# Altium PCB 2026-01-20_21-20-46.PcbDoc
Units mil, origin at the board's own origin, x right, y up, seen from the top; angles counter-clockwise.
Board outline 2766 x 1978 mil, 4 copper layers (Top Layer, MidLayer1, MidLayer2, Bottom Layer); 17 components, 9 nets, 37 pads, 37 vias.
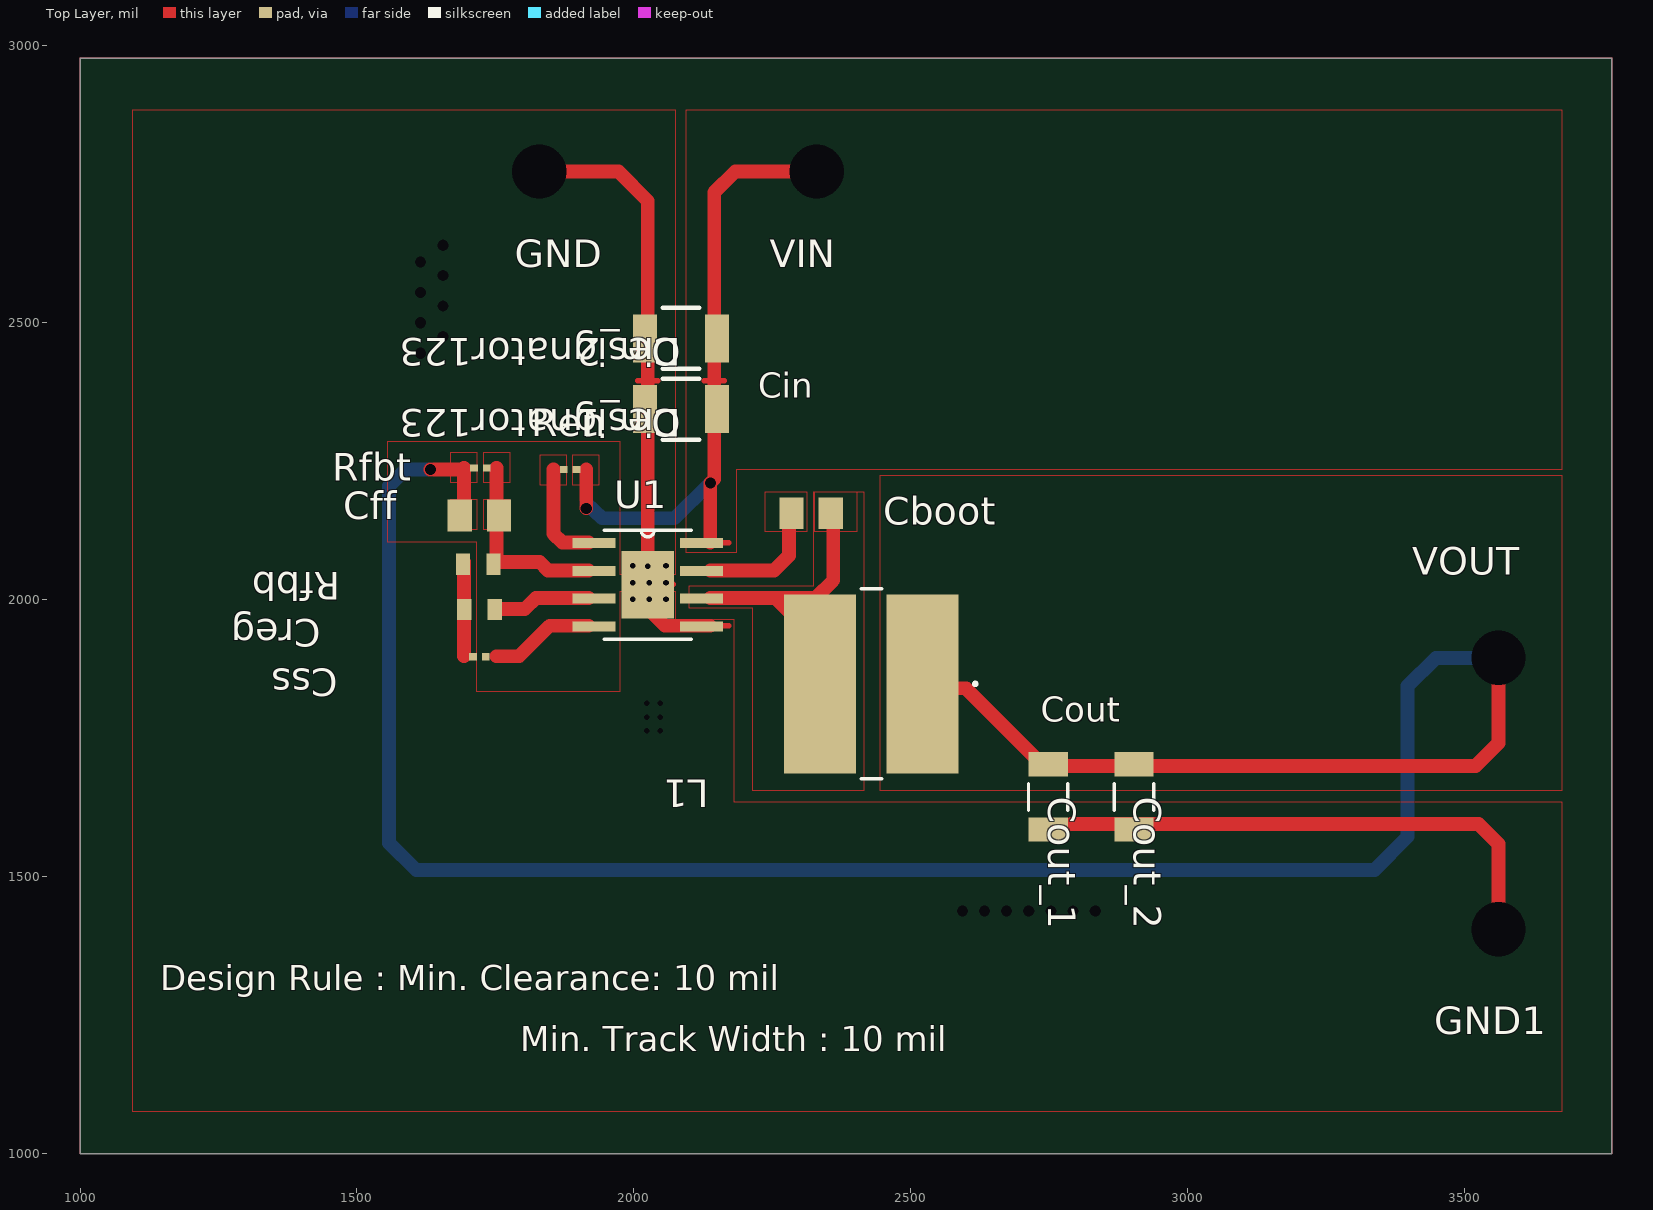
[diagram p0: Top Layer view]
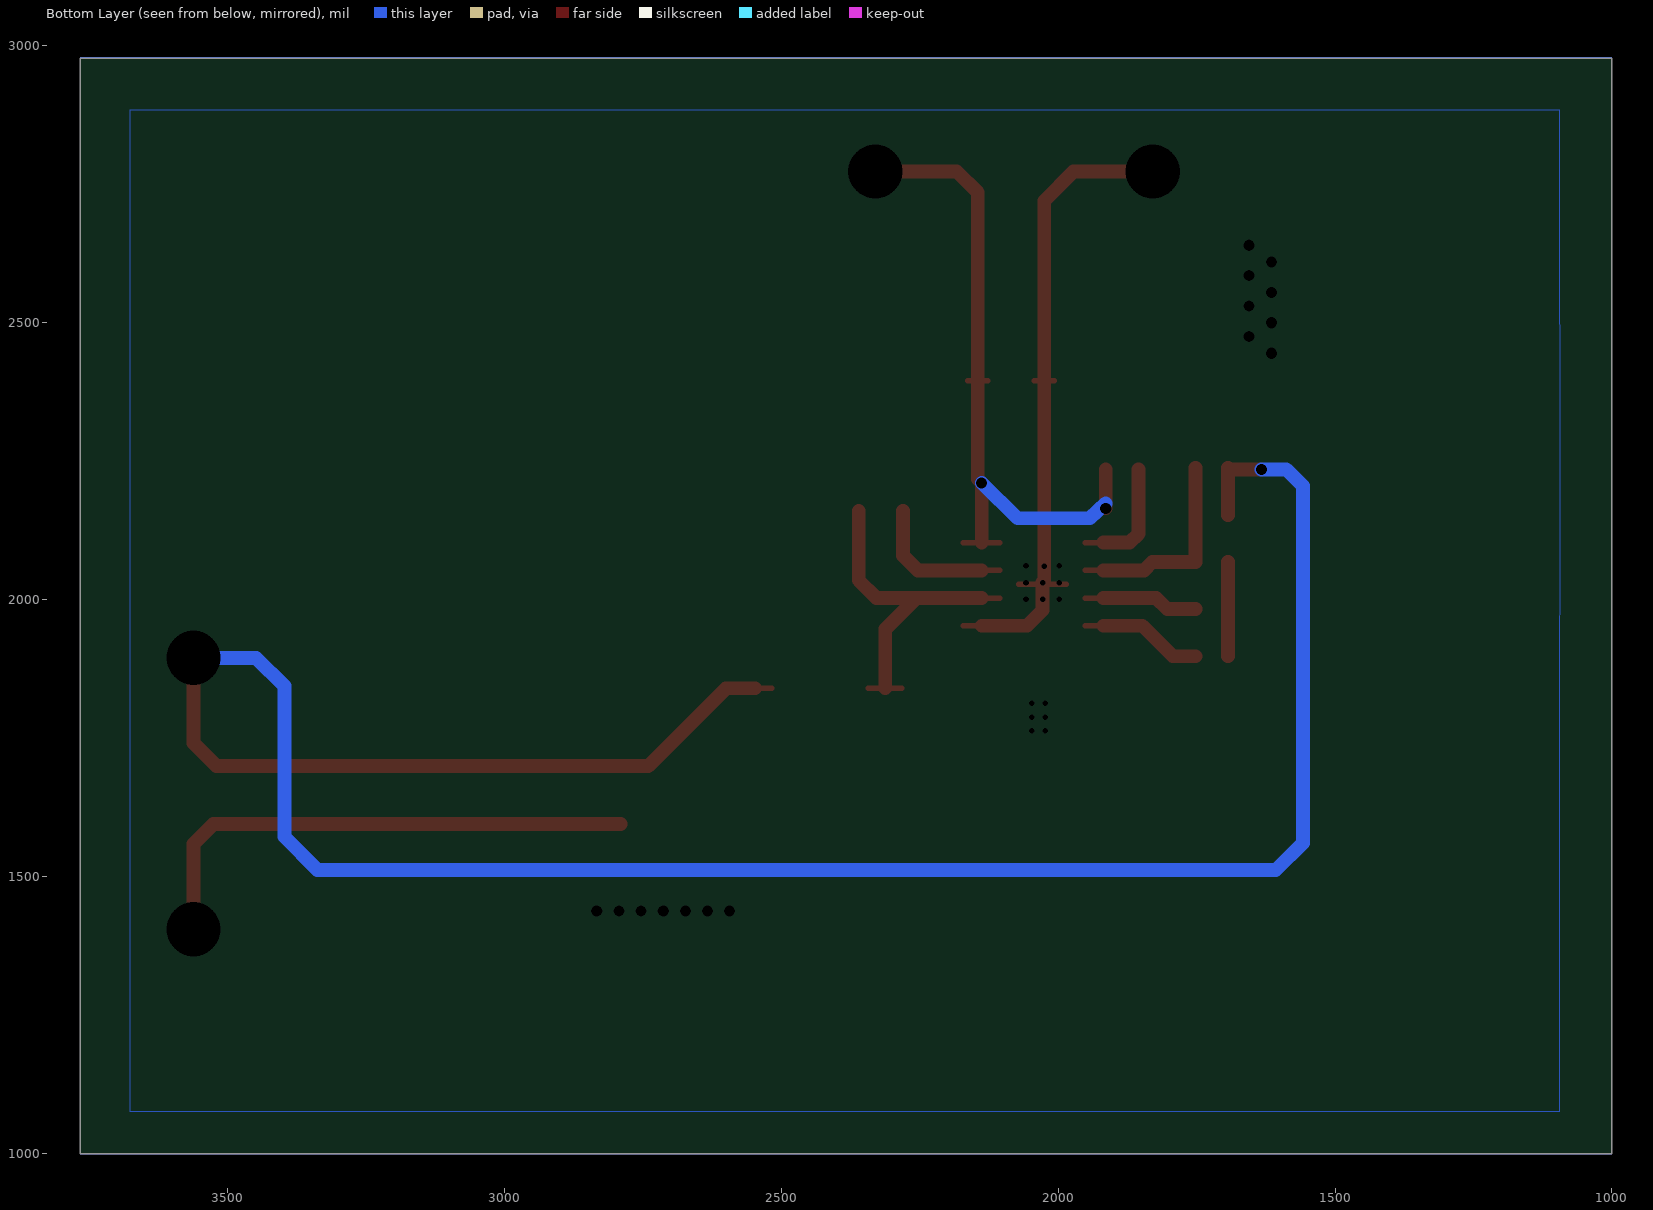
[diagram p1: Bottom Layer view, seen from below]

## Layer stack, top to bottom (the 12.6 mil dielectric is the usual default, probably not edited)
Top Layer: signal copper 1.4
Dielectric: core 12.6, FR-4, Dk 4.8
MidLayer1: signal copper 1.4
Dielectric: prepreg 12.6, FR-4, Dk 4.8
MidLayer2: signal copper 1.4
Dielectric: core 12.6, FR-4, Dk 4.8
Bottom Layer: signal copper 1.4

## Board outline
1000,1000 3766,1000 3766,2978 1000,2978

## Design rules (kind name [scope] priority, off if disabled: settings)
PlaneConnect [All] p0: scope1count=1 scope1_0_kind=Board scope1_0_value=Board scope2count=1 scope2_0_kind=Board scope2_0_value=Board commentlength=0 planeconnectstyle=Direct reliefexpansion=20 reliefentries=4 reliefconductorwidth=10 reliefairgap=10
PlaneConnect [All] p1: planeconnectstyle=Direct reliefexpansion=20 reliefentries=4 reliefconductorwidth=10 reliefairgap=10
PolygonConnect [All] p0: scope1count=1 scope1_0_kind=Board scope1_0_value=Board scope2count=1 scope2_0_kind=Board scope2_0_value=Board commentlength=0 connectstyle=Direct reliefconductorwidth=10 reliefentries=4 polygonreliefangle="90 Angle"
PolygonConnect [All] p1: connectstyle=Direct reliefconductorwidth=10 reliefentries=4 polygonreliefangle="90 Angle"

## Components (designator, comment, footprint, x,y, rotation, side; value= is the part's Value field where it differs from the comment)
Cboot "" 0805 2320,2156 r0 top
Cff "" 0805 1721,2152 r0 top
Cin_1 "" 1210_280 2085,2344 r180 top
Cin_2 "" 1210_280 2085,2472 r180 top
Cout_1 "" 1206 2748,1644 r270 top
Cout_2 "" 1206 2903,1644 r270 top
Creg "" 0603 1721,1982 r180 top
Css "" 0201 1721,1897 r180 top
GND "" TP-1502 1828,2772 r0 top
GND1 "" TP-1502 3560,1405 r0 top
L1 "" VLP8040 2429,1848 r180 top
Ren "" 0201 1885,2235 r0 top
Rfbb "" 0603 1719,2064 r180 top
Rfbt "" 0201 1723,2238 r0 top
U1 "" R-PDSO-G8 2025,2027 r0 top
VIN "" TP-1502 2328,2772 r0 top
VOUT "" TP-1502 3560,1894 r0 top

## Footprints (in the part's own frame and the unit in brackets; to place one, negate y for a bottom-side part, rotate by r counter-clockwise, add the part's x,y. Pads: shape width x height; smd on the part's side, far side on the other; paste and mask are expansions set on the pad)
0201 [mil]
  rect 14x13 smd: 1(-11.5,0) 2(11.5,0)
0603 [mil]
  rect 26x38 smd: 1(-27.5,0) 2(27.5,0)
0805 [mil]
  rect 44x57 smd: 1(-35.5,0) 2(35.5,0)
1206 [mil]
  rect 44x71 smd: 1(-59,0) 2(59,0)
  silkscreen extent -24,-36 24,36
1210_280 [mm]
  rect 1.1x2.2 smd: 1(-1.65,0) 2(1.65,0)
  silkscreen extent -0.84,-1.4 0.84,1.4
R-PDSO-G8 [mil]
  rect 78x18.14 smd: 1(-97,75) 2(-97,25) 3(-97,-25) 4(-97,-75) 5(97,-75) 6(97,-25) 7(97,25) 8(97,75)
  rect 94x122 smd: 9(0,0)
  silkscreen extent -78,-98 78,98
TP-1502 [mil]
  round 65 hole 32: 1(0,0)
VLP8040 [mil]
  rect 130x323 smd: 1(-92.5,0) 2(92.5,0)
  silkscreen extent -190,-172 19,172

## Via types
v1: diameter 0, hole 20, Top Layer to Bottom Layer, 18 vias
v2: diameter 0, hole 10, Top Layer to Bottom Layer, 15 vias
v3: diameter 0, hole 98, Top Layer to Bottom Layer, 4 vias

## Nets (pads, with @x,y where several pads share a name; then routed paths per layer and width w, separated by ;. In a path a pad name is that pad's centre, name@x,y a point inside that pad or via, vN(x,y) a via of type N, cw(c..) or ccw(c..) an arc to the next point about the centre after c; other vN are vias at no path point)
0: Cin_1.2 Cin_2.2 Cout_1.2 Cout_2.2 Creg.2 Css.2 GND1.1 GND.1 Rfbb.2 U1.5 U1.9 | length 2382.7
  Top Layer w10: v3(1829,2773) GND.1@1829,2778 ; U1.9@1985,2028 U1.9@2071,2028 ; 2007,2395 2043,2395 ; U1.9@2025,2034 v2(2028,2031) ; U1.5@2105,1953 2171,1953
  Top Layer w25: 1693,1898 1693,1983 Rfbb.2@1693,2068 ; v3(1829,2773) 1972,2773 2025,2720 2025,2395 v2(2025,2060) U1.9@2025,2034 ; v2(2028,2031) 2028,2028 v2(2028,2001) 2028,1981 2056,1953 U1.5@2138,1953 ; 2790,1595 3525,1595 3561,1559 v3(3561,1405)
  other v1: 2593,1438 2633,1438 2673,1438 2713,1438 2753,1438 2793,1438 2833,1438 1615,2445 1655,2475 1615,2500 1655,2530 1615,2555 1655,2585 1615,2610 1655,2640
  other v2: 2023,1763 2048,1763 2023,1788 2048,1788 2023,1813 2048,1813 1998,2001 2058,2001 1998,2031 2058,2031 1998,2061 2058,2061
1: Cin_1.1 Cin_2.1 Ren.2 U1.8 VIN.1 | length 1268.5
  Top Layer w10: U1.8@2105,2103 2171,2103 ; 2127,2395 2163,2395
  Top Layer w25: v1(1914,2165) 1914,2235 ; U1.8@2138,2103 v1(2138,2211) 2145,2218 2145,2395 2145,2735 2183,2773 v3(2330,2773)
  Bottom Layer w25: 1914,2174 1943,2147 2073,2147 v1(2138,2211)
2: Css.1 U1.4 | length 254.8
  Top Layer w10: 1885,1953 U1.4@1951,1953
  Top Layer w25: 1752,1898 1793,1898 1848,1953 U1.4@1918,1953
3: Creg.1 U1.3 | length 240.3
  Top Layer w10: 1885,2003 U1.3@1951,2003
  Top Layer w25: Creg.1@1752,1983 1803,1983 1823,2003 U1.3@1918,2003
4: Ren.1 U1.1 | length 251.6
  Top Layer w10: 1885,2103 U1.1@1951,2103
  Top Layer w25: 1855,2235 1855,2119 1871,2103 U1.1@1918,2103
5: Cff.2 Rfbb.1 Rfbt.2 U1.2 | length 408.2
  Top Layer w10: 1885,2053 U1.2@1951,2053
  Top Layer w25: 1752,2238 1752,2153 1752,2068 1830,2068 1845,2053 U1.2@1918,2053
6: Cff.1 Cout_1.1 Cout_2.1 L1.1 Rfbt.1 VOUT.1 | length 4517.7
  Top Layer w10: L1.1@2517,1840 L1.1@2578,1840
  Top Layer w25: v1(1633,2235) 1689,2235 ; Cff.1@1693,2153 1693,2238 ; L1.1@2547,1840 2600,1840 2740,1700 2790,1700 3520,1700 3561,1741 v3(3561,1895)
  Bottom Layer w25: v1(1633,2235) 1588,2235 1558,2205 1558,1561 1607,1512 3337,1512 3397,1572 3397,1844 3448,1895 v3(3561,1895)
7: Cboot.2 L1.2 U1.6 | length 673.5
  Top Layer w10: U1.6@2105,2003 2171,2003 ; L1.2@2282,1840 L1.2@2343,1840
  Top Layer w25: U1.6@2138,2003 2256,2003 ; L1.2@2312,1840 2312,1947 2256,2003 ; Cboot.2@2360,2160 2360,2035 2328,2003 2256,2003
8: Cboot.1 U1.7 | length 299.2
  Top Layer w10: U1.7@2105,2053 2171,2053
  Top Layer w25: U1.7@2138,2053 2253,2053 2280,2080 Cboot.1@2280,2160

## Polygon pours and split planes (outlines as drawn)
1 on Top Layer " " (solid, pour order 0): 1890,2207 1890,2262 1937,2262 1937,2207
4 on Top Layer " " (solid, pour order 1): 1831,2207 1831,2262 1878,2262 1878,2207
5 on Top Layer " " (solid, pour order 2): 1729,2126 1729,2181 1776,2181 1776,2126
6 on Top Layer " " (solid, pour order 3): 1669,2126 1669,2181 1716,2181 1716,2126
5 on Top Layer " " (solid, pour order 4): 1729,2211 1729,2266 1776,2266 1776,2211
6 on Top Layer " " (solid, pour order 5): 1669,2211 1669,2266 1716,2266 1716,2211
8 on Top Layer " " (solid, pour order 6): 2237,2123 2237,2195 2312,2195 2312,2123
7 on Top Layer " " (solid, pour order 7): 2327,2123 2327,2195 2402,2195 2402,2123
1 on Top Layer " " (solid, pour order 8): 2095,2885 3675,2885 3675,2235 2185,2235 2185,2085 2095,2085
6 on Top Layer " " (solid, pour order 9): 2445,2225 3675,2225 3675,1655 2445,1655
7 on Top Layer " " (solid, pour order 10): 2100,2025 2325,2025 2325,2195 2415,2195 2415,1655 2215,1655 2215,1985 2100,1985
0 on Top Layer " " (solid, pour order 14): 2075,2885 2075,2045 1975,2045 1975,2285 1555,2285 1555,2105 1715,2105 1715,1835 1975,1835 1975,2015 2075,2015 2075,1965 2180,1965 2180,1635 3675,1635 3675,1075 1095,1075 1095,2885
0 on Bottom Layer " " (solid, pour order 11): 1095,1075 3675,1075 3675,2885 1095,2885 1095,2505 1094,2489 1095,1455
0 on MidLayer2 " " (solid, pour order 12): 1095,1075 3675,1075 3675,2885 1095,2885 1095,2505 1094,2489 1095,1975
0 on MidLayer1 " " (solid, pour order 13): 1095,1075 3675,1075 3675,2885 1095,2885

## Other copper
Multi-Layer:
  lines w1: 1000,1000 1000,2978.5 3765.9,2978.5 3765.9,1000 1000,1000

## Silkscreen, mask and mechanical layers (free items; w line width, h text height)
Top Overlay:
  text "Cin" at 2225,2365 h45
  text "Cout" at 2735,1780 h45
  text "Design Rule : Min. Clearance: 10 mil" at 1145,1295 h45
  text "Min. Track Width : 10 mil" at 1795,1185 h45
